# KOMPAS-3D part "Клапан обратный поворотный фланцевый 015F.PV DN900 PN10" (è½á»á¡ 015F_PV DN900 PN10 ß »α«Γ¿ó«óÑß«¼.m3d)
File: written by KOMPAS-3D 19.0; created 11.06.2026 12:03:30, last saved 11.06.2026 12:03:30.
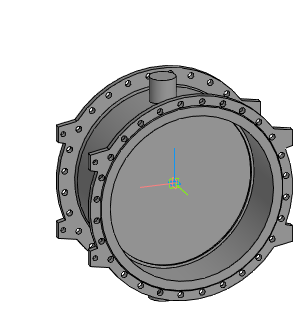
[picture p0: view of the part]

Document properties: Автор: Энергия; Полное имя файла: Z:\3.Личные\kachalov\001_3d для проектировщиков\5.5 Тип 015F.PV Клапан обратный поворотный с двумя эксцентриками\_stp_Клапан 015F.PV DN300-DN1200 с противовесом\Клапан 015F_PV DN900 PN10 с противовесом.m3d

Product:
- Part/product: Клапан обратный поворотный фланцевый 015F.PV DN900 PN10

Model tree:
1. Операция без истории:1
2. Сплайн:1
     Координата Y = 30; Координата Z = 450; Вес = 1; Координата X = 900; Координата Y = 148.487; Координата Z = 450; Вес = 0.333333; Координата X = 900; Координата Y = 148.487; Координата Z = -450; Вес = 0.333333; Координата Y = 30; Координата Z = -450; Вес = 1; Координата X = -900; Координата Y = -88.4872; Координата Z = -450; Вес = 0.333333; Координата X = -900; Координата Y = -88.4872; Координата Z = 450; Вес = 0.333333; Порядок = 4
